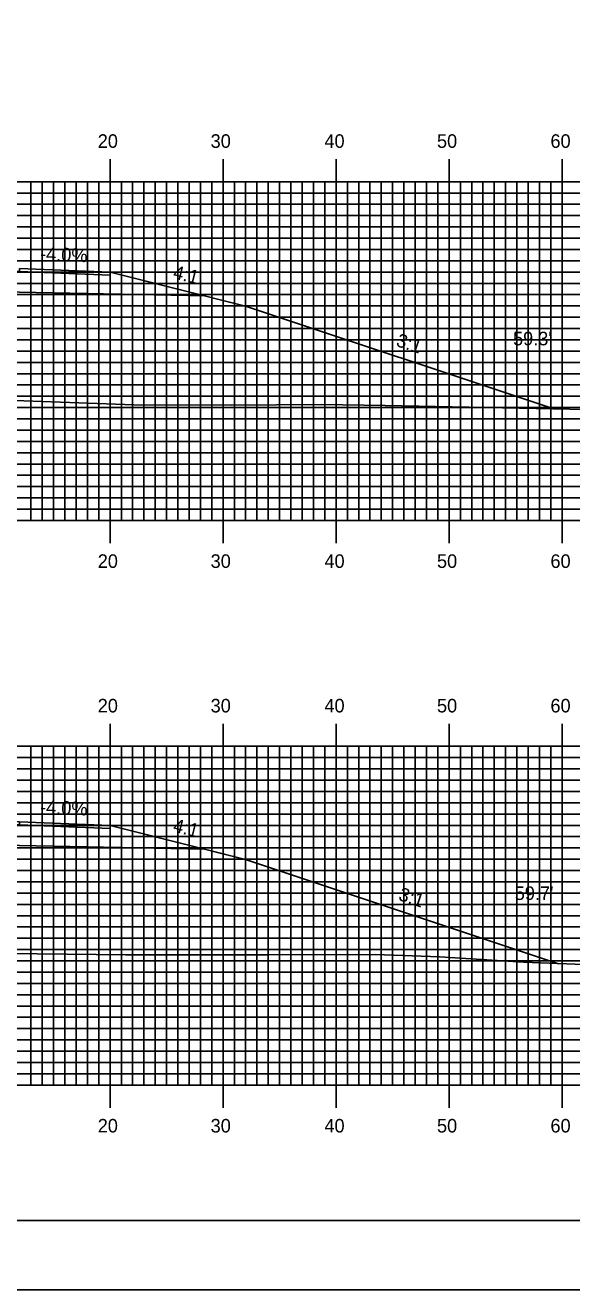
# Model space of a CAD drawing. Extents: x 1807438 to 1807782, y 442591 to 442811.
# Drawn here: x 1807616.8 to 1807665.1, y 442590.5 to 442702.5 of the extents above; entities that cross this region are included whole.
import ezdxf

# ---------------------------------------------------------------- set-up
doc = ezdxf.new("R2010")
doc.units = 0
for name, color, linetype in [('ANNOTATION', 7, 'Continuous'), ('BORDER', 7, 'Continuous'), ('D_Roadway_Centerline', 7, 'Continuous'), ('D_Roadway_Edge_Shoulder', 7, 'Continuous'), ('D_Roadway_SlopeLines', 7, 'Continuous'), ('D_Roadway_SubGrade', 7, 'Continuous'), ('D_Text_Standard', 7, 'Continuous'), ('H_V ANNOTATION', 7, 'Continuous'), ('MAJOR', 7, 'Continuous'), ('MINOR', 7, 'Continuous'), ('PLOT BOUNDARY', 7, 'Continuous'), ('S_Roadway_Centerline', 7, 'Continuous')]:
    doc.layers.add(name, color=color, linetype=linetype)

msp = doc.modelspace()

# ---------------------------------------------------------------- linework, layer by layer
at = {"layer": 'BORDER'}
msp.add_lwpolyline([(1807454.67, 442596.67), (1807774.67, 442596.67), (1807774.67, 442806.67), (1807454.67, 442806.67)], close=True, dxfattribs=at)
at = {"layer": 'D_Roadway_Centerline'}
msp.add_lwpolyline([(1807550.27, 442621.31), (1807572.27, 442628.65), (1807575.91, 442629.56), (1807584.27, 442631.65), (1807592.27, 442631.97), (1807604.27, 442632.21), (1807616.27, 442631.97), (1807624.27, 442631.65), (1807632.63, 442629.56), (1807636.27, 442628.65), (1807663.94, 442619.42)], dxfattribs=at)
at = {"layer": 'D_Roadway_Edge_Shoulder'}
for points in [[(1807616.27, 442680.97), (1807624.27, 442680.65), (1807624.27, 442680.4), (1807616.27, 442680.72)], [(1807616.27, 442631.97), (1807624.27, 442631.65), (1807624.27, 442631.4), (1807616.27, 442631.72)]]:
    msp.add_lwpolyline(points, close=True, dxfattribs=at)
at = {"layer": 'D_Roadway_SlopeLines'}
for points in [[(1807624.27, 442680.65), (1807636.27, 442677.65), (1807663.54, 442668.56)], [(1807624.27, 442631.65), (1807636.27, 442628.65), (1807663.94, 442619.42)]]:
    msp.add_lwpolyline(points, dxfattribs=at)
at = {"layer": 'D_Roadway_SubGrade'}
msp.add_lwpolyline([(1807584.27, 442680.65), (1807584.27, 442680.4), (1807592.27, 442680.72), (1807604.27, 442680.96), (1807616.27, 442680.72), (1807624.27, 442680.4), (1807624.27, 442680.65), (1807632.63, 442678.56), (1807616.27, 442678.88), (1807604.27, 442679.12), (1807592.27, 442678.88), (1807575.91, 442678.56)], dxfattribs=at)
msp.add_lwpolyline([(1807592.27, 442629.88), (1807575.91, 442629.56), (1807584.27, 442631.65), (1807584.27, 442631.4), (1807592.27, 442631.72), (1807604.27, 442631.96), (1807616.27, 442631.72), (1807624.27, 442631.4), (1807624.27, 442631.65), (1807632.63, 442629.56), (1807616.27, 442629.88), (1807604.27, 442630.12)], close=True, dxfattribs=at)
at = {"layer": 'MAJOR'}
for p, q in [((1807624.27, 442690.67), (1807624.27, 442688.67)), ((1807634.27, 442690.67), (1807634.27, 442688.67)), ((1807644.27, 442690.67), (1807644.27, 442688.67)), ((1807654.27, 442690.67), (1807654.27, 442688.67)), ((1807664.27, 442690.67), (1807664.27, 442688.67)), ((1807464.27, 442688.67), (1807744.27, 442688.67)), ((1807464.27, 442688.67), (1807744.27, 442688.67)), ((1807624.27, 442658.67), (1807624.27, 442688.67)), ((1807634.27, 442658.67), (1807634.27, 442688.67)), ((1807644.27, 442658.67), (1807644.27, 442688.67)), ((1807654.27, 442658.67), (1807654.27, 442688.67)), ((1807664.27, 442658.67), (1807664.27, 442688.67)), ((1807464.27, 442683.67), (1807744.27, 442683.67)), ((1807464.27, 442678.67), (1807744.27, 442678.67)), ((1807464.27, 442673.67), (1807744.27, 442673.67)), ((1807464.27, 442668.67), (1807744.27, 442668.67)), ((1807464.27, 442663.67), (1807744.27, 442663.67)), ((1807464.27, 442658.67), (1807744.27, 442658.67)), ((1807464.27, 442658.67), (1807744.27, 442658.67)), ((1807624.27, 442656.66), (1807624.27, 442658.67)), ((1807634.27, 442656.66), (1807634.27, 442658.67)), ((1807644.27, 442656.66), (1807644.27, 442658.67)), ((1807654.27, 442656.66), (1807654.27, 442658.67)), ((1807664.27, 442656.66), (1807664.27, 442658.67)), ((1807624.27, 442640.67), (1807624.27, 442638.67)), ((1807634.27, 442640.67), (1807634.27, 442638.67)), ((1807644.27, 442640.67), (1807644.27, 442638.67)), ((1807654.27, 442640.67), (1807654.27, 442638.67)), ((1807664.27, 442640.67), (1807664.27, 442638.67)), ((1807464.27, 442638.67), (1807744.27, 442638.67)), ((1807464.27, 442638.67), (1807744.27, 442638.67)), ((1807624.27, 442608.67), (1807624.27, 442638.67)), ((1807634.27, 442608.67), (1807634.27, 442638.67)), ((1807644.27, 442608.67), (1807644.27, 442638.67)), ((1807654.27, 442608.67), (1807654.27, 442638.67)), ((1807664.27, 442608.67), (1807664.27, 442638.67)), ((1807464.27, 442633.67), (1807744.27, 442633.67)), ((1807464.27, 442628.67), (1807744.27, 442628.67)), ((1807464.27, 442623.67), (1807744.27, 442623.67)), ((1807464.27, 442618.67), (1807744.27, 442618.67)), ((1807464.27, 442613.67), (1807744.27, 442613.67)), ((1807464.27, 442608.67), (1807744.27, 442608.67)), ((1807464.27, 442608.67), (1807744.27, 442608.67)), ((1807624.27, 442606.66), (1807624.27, 442608.67)), ((1807634.27, 442606.66), (1807634.27, 442608.67)), ((1807644.27, 442606.66), (1807644.27, 442608.67)), ((1807654.27, 442606.66), (1807654.27, 442608.67)), ((1807664.27, 442606.66), (1807664.27, 442608.67))]:
    msp.add_line(p, q, dxfattribs=at)
at = {"layer": 'MINOR'}
for p, q in [((1807617.27, 442658.67), (1807617.27, 442688.67)), ((1807618.27, 442658.67), (1807618.27, 442688.67)), ((1807619.27, 442658.67), (1807619.27, 442688.67)), ((1807620.27, 442658.67), (1807620.27, 442688.67)), ((1807621.27, 442658.67), (1807621.27, 442688.67)), ((1807622.27, 442658.67), (1807622.27, 442688.67)), ((1807623.27, 442658.67), (1807623.27, 442688.67)), ((1807625.27, 442658.67), (1807625.27, 442688.67)), ((1807626.27, 442658.67), (1807626.27, 442688.67)), ((1807627.27, 442658.67), (1807627.27, 442688.67)), ((1807628.27, 442658.67), (1807628.27, 442688.67)), ((1807629.27, 442658.67), (1807629.27, 442688.67)), ((1807630.27, 442658.67), (1807630.27, 442688.67)), ((1807631.27, 442658.67), (1807631.27, 442688.67)), ((1807632.27, 442658.67), (1807632.27, 442688.67)), ((1807633.27, 442658.67), (1807633.27, 442688.67)), ((1807635.27, 442658.67), (1807635.27, 442688.67)), ((1807636.27, 442658.67), (1807636.27, 442688.67)), ((1807637.27, 442658.67), (1807637.27, 442688.67)), ((1807638.27, 442658.67), (1807638.27, 442688.67)), ((1807639.27, 442658.67), (1807639.27, 442688.67)), ((1807640.27, 442658.67), (1807640.27, 442688.67)), ((1807641.27, 442658.67), (1807641.27, 442688.67)), ((1807642.27, 442658.67), (1807642.27, 442688.67)), ((1807643.27, 442658.67), (1807643.27, 442688.67)), ((1807645.27, 442658.67), (1807645.27, 442688.67)), ((1807646.27, 442658.67), (1807646.27, 442688.67)), ((1807647.27, 442658.67), (1807647.27, 442688.67)), ((1807648.27, 442658.67), (1807648.27, 442688.67)), ((1807649.27, 442658.67), (1807649.27, 442688.67)), ((1807650.27, 442658.67), (1807650.27, 442688.67)), ((1807651.27, 442658.67), (1807651.27, 442688.67)), ((1807652.27, 442658.67), (1807652.27, 442688.67)), ((1807653.27, 442658.67), (1807653.27, 442688.67)), ((1807655.27, 442658.67), (1807655.27, 442688.67)), ((1807656.27, 442658.67), (1807656.27, 442688.67)), ((1807657.27, 442658.67), (1807657.27, 442688.67)), ((1807658.27, 442658.67), (1807658.27, 442688.67)), ((1807659.27, 442658.67), (1807659.27, 442688.67)), ((1807660.27, 442658.67), (1807660.27, 442688.67)), ((1807661.27, 442658.67), (1807661.27, 442688.67)), ((1807662.27, 442658.67), (1807662.27, 442688.67)), ((1807663.27, 442658.67), (1807663.27, 442688.67)), ((1807464.27, 442687.67), (1807744.27, 442687.67)), ((1807464.27, 442686.67), (1807744.27, 442686.67)), ((1807464.27, 442685.67), (1807744.27, 442685.67)), ((1807464.27, 442684.67), (1807744.27, 442684.67)), ((1807464.27, 442682.67), (1807744.27, 442682.67)), ((1807464.27, 442681.67), (1807744.27, 442681.67)), ((1807464.27, 442680.67), (1807744.27, 442680.67)), ((1807464.27, 442679.67), (1807744.27, 442679.67)), ((1807464.27, 442677.67), (1807744.27, 442677.67)), ((1807464.27, 442676.67), (1807744.27, 442676.67)), ((1807464.27, 442675.67), (1807744.27, 442675.67)), ((1807464.27, 442674.67), (1807744.27, 442674.67)), ((1807464.27, 442672.67), (1807744.27, 442672.67)), ((1807464.27, 442671.67), (1807744.27, 442671.67)), ((1807464.27, 442670.67), (1807744.27, 442670.67)), ((1807464.27, 442669.67), (1807744.27, 442669.67)), ((1807464.27, 442667.67), (1807744.27, 442667.67)), ((1807464.27, 442666.67), (1807744.27, 442666.67)), ((1807464.27, 442665.67), (1807744.27, 442665.67)), ((1807464.27, 442664.67), (1807744.27, 442664.67)), ((1807464.27, 442662.67), (1807744.27, 442662.67)), ((1807464.27, 442661.67), (1807744.27, 442661.67)), ((1807464.27, 442660.67), (1807744.27, 442660.67)), ((1807464.27, 442659.67), (1807744.27, 442659.67)), ((1807617.27, 442608.67), (1807617.27, 442638.67)), ((1807618.27, 442608.67), (1807618.27, 442638.67)), ((1807619.27, 442608.67), (1807619.27, 442638.67)), ((1807620.27, 442608.67), (1807620.27, 442638.67)), ((1807621.27, 442608.67), (1807621.27, 442638.67)), ((1807622.27, 442608.67), (1807622.27, 442638.67)), ((1807623.27, 442608.67), (1807623.27, 442638.67)), ((1807625.27, 442608.67), (1807625.27, 442638.67)), ((1807626.27, 442608.67), (1807626.27, 442638.67)), ((1807627.27, 442608.67), (1807627.27, 442638.67)), ((1807628.27, 442608.67), (1807628.27, 442638.67)), ((1807629.27, 442608.67), (1807629.27, 442638.67)), ((1807630.27, 442608.67), (1807630.27, 442638.67)), ((1807631.27, 442608.67), (1807631.27, 442638.67)), ((1807632.27, 442608.67), (1807632.27, 442638.67)), ((1807633.27, 442608.67), (1807633.27, 442638.67)), ((1807635.27, 442608.67), (1807635.27, 442638.67)), ((1807636.27, 442608.67), (1807636.27, 442638.67)), ((1807637.27, 442608.67), (1807637.27, 442638.67)), ((1807638.27, 442608.67), (1807638.27, 442638.67)), ((1807639.27, 442608.67), (1807639.27, 442638.67)), ((1807640.27, 442608.67), (1807640.27, 442638.67)), ((1807641.27, 442608.67), (1807641.27, 442638.67)), ((1807642.27, 442608.67), (1807642.27, 442638.67)), ((1807643.27, 442608.67), (1807643.27, 442638.67)), ((1807645.27, 442608.67), (1807645.27, 442638.67)), ((1807646.27, 442608.67), (1807646.27, 442638.67)), ((1807647.27, 442608.67), (1807647.27, 442638.67)), ((1807648.27, 442608.67), (1807648.27, 442638.67)), ((1807649.27, 442608.67), (1807649.27, 442638.67)), ((1807650.27, 442608.67), (1807650.27, 442638.67)), ((1807651.27, 442608.67), (1807651.27, 442638.67)), ((1807652.27, 442608.67), (1807652.27, 442638.67)), ((1807653.27, 442608.67), (1807653.27, 442638.67)), ((1807655.27, 442608.67), (1807655.27, 442638.67)), ((1807656.27, 442608.67), (1807656.27, 442638.67)), ((1807657.27, 442608.67), (1807657.27, 442638.67)), ((1807658.27, 442608.67), (1807658.27, 442638.67)), ((1807659.27, 442608.67), (1807659.27, 442638.67)), ((1807660.27, 442608.67), (1807660.27, 442638.67)), ((1807661.27, 442608.67), (1807661.27, 442638.67)), ((1807662.27, 442608.67), (1807662.27, 442638.67)), ((1807663.27, 442608.67), (1807663.27, 442638.67)), ((1807464.27, 442637.67), (1807744.27, 442637.67)), ((1807464.27, 442636.67), (1807744.27, 442636.67)), ((1807464.27, 442635.67), (1807744.27, 442635.67)), ((1807464.27, 442634.67), (1807744.27, 442634.67)), ((1807464.27, 442632.67), (1807744.27, 442632.67)), ((1807464.27, 442631.67), (1807744.27, 442631.67)), ((1807464.27, 442630.67), (1807744.27, 442630.67)), ((1807464.27, 442629.67), (1807744.27, 442629.67)), ((1807464.27, 442627.67), (1807744.27, 442627.67)), ((1807464.27, 442626.67), (1807744.27, 442626.67)), ((1807464.27, 442625.67), (1807744.27, 442625.67)), ((1807464.27, 442624.67), (1807744.27, 442624.67)), ((1807464.27, 442622.67), (1807744.27, 442622.67)), ((1807464.27, 442621.67), (1807744.27, 442621.67)), ((1807464.27, 442620.67), (1807744.27, 442620.67)), ((1807464.27, 442619.67), (1807744.27, 442619.67)), ((1807464.27, 442617.67), (1807744.27, 442617.67)), ((1807464.27, 442616.67), (1807744.27, 442616.67)), ((1807464.27, 442615.67), (1807744.27, 442615.67)), ((1807464.27, 442614.67), (1807744.27, 442614.67)), ((1807464.27, 442612.67), (1807744.27, 442612.67)), ((1807464.27, 442611.67), (1807744.27, 442611.67)), ((1807464.27, 442610.67), (1807744.27, 442610.67)), ((1807464.27, 442609.67), (1807744.27, 442609.67))]:
    msp.add_line(p, q, dxfattribs=at)
at = {"layer": 'PLOT BOUNDARY'}
msp.add_lwpolyline([(1807438.49, 442590.55), (1807778.49, 442590.55), (1807778.49, 442810.55), (1807438.49, 442810.55)], close=True, dxfattribs=at)
at = {"layer": 'S_Roadway_Centerline'}
for points in [[(1807543.03, 442670.64), (1807558.83, 442670.39), (1807562.82, 442670.28), (1807573.14, 442669.98), (1807583.75, 442670.32), (1807584.48, 442670.34), (1807595.61, 442669.99), (1807607.18, 442669.59), (1807608.44, 442669.57), (1807610.13, 442669.5), (1807626.36, 442668.9), (1807635.04, 442668.88), (1807642.94, 442668.94), (1807648.6, 442668.86), (1807666.43, 442668.5)], [(1807542.11, 442621.43), (1807545.92, 442621.36), (1807550.02, 442621.31), (1807568.49, 442621.2), (1807575.25, 442621.04), (1807583.79, 442621.05), (1807600.51, 442621.06), (1807602.75, 442620.99), (1807604.87, 442620.9), (1807615.2, 442620.31), (1807625.66, 442620.19), (1807638.28, 442620.19), (1807647.75, 442620.23), (1807653.42, 442620.03), (1807660.85, 442619.54), (1807668.49, 442619.26)]]:
    msp.add_lwpolyline(points, dxfattribs=at)

# ---------------------------------------------------------------- texts
at = {"layer": 'ANNOTATION'}
for s, rotation, p in [('-4.0%', 357.7094, (1807618.06, 442681.7)), ('4:1', 345.9638, (1807629.78, 442680.13)), ('3:1', 341.5652, (1807649.51, 442674.14)), ('-4.0%', 357.7094, (1807618.06, 442632.7)), ('4:1', 345.9638, (1807629.78, 442631.13)), ('3:1', 341.5652, (1807649.71, 442625.08))]:
    msp.add_text(s, height=1.2, rotation=rotation, dxfattribs=at).set_placement(p)
at = {"layer": 'D_Text_Standard'}
for s, p in [("59.3'", (1807659.93, 442674.18)), ("59.7'", (1807660.08, 442625.06))]:
    msp.add_text(s, height=1.2, dxfattribs=at).set_placement(p)
at = {"layer": 'H_V ANNOTATION'}
for s, p in [('20', (1807623.18, 442691.67)), ('30', (1807633.17, 442691.67)), ('40', (1807643.24, 442691.67)), ('50', (1807653.2, 442691.67)), ('60', (1807663.24, 442691.67)), ('20', (1807623.18, 442654.47)), ('30', (1807633.17, 442654.47)), ('40', (1807643.24, 442654.47)), ('50', (1807653.2, 442654.47)), ('60', (1807663.24, 442654.47)), ('20', (1807623.18, 442641.67)), ('30', (1807633.17, 442641.67)), ('40', (1807643.24, 442641.67)), ('50', (1807653.2, 442641.67)), ('60', (1807663.24, 442641.67)), ('20', (1807623.18, 442604.47)), ('30', (1807633.17, 442604.47)), ('40', (1807643.24, 442604.47)), ('50', (1807653.2, 442604.47)), ('60', (1807663.24, 442604.47))]:
    msp.add_text(s, height=1.2, dxfattribs=at).set_placement(p)

doc.saveas('drawing.dxf')
